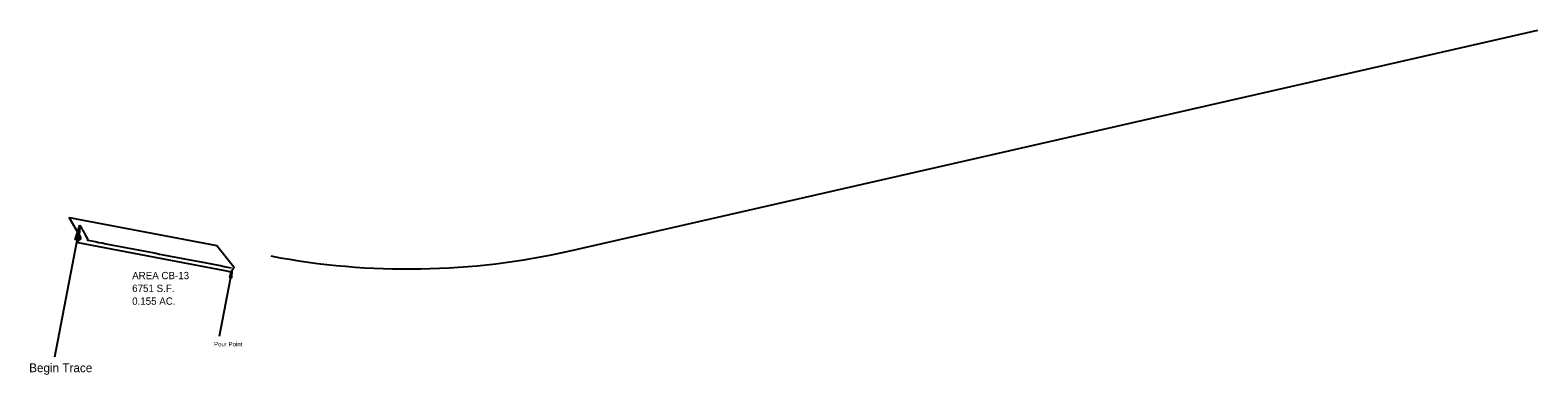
# Model space of a CAD drawing. Extents: x 3422 to 5489, y 2878 to 3350.
import ezdxf

# ---------------------------------------------------------------- set-up
doc = ezdxf.new("R2010")
doc.units = 0
for name, color, linetype in [('Default', 7, 'Continuous'), ('DESIGN - CENTERLINE - Proposed', 7, 'Continuous'), ('DESIGN - SCRATCH - User 1', 7, 'Continuous'), ('SURVEY - CENTERLINE - Preliminary', 7, 'Continuous'), ('SURVEY - CENTERLINE - Preliminary Text', 7, 'Continuous'), ('SURVEY - DRAINAGE - Area Shapes', 7, 'Continuous')]:
    doc.layers.add(name, color=color, linetype=linetype)

msp = doc.modelspace()

# ---------------------------------------------------------------- linework, layer by layer
at = {"layer": 'DESIGN - CENTERLINE - Proposed'}
msp.add_line((4162.4, 3048), (5488.9, 3350.1), dxfattribs=at)
msp.add_arc((3940.3, 4023), 1000, 259.1667, 282.8334, dxfattribs=at)
at = {"layer": 'DESIGN - SCRATCH - User 1'}
msp.add_line((3698.9, 3020.8), (3681.4, 2930.3), dxfattribs=at)
msp.add_lwpolyline([(3698.9, 3020.8), (3698.3, 3010.7), (3697.3, 3012.2), (3695.8, 3011.2)], close=True, dxfattribs=at)
msp.add_lwpolyline([(3698.9, 3020.8), (3698.3, 3010.7), (3697.3, 3012.2), (3695.8, 3011.2), (3698.9, 3020.8)], dxfattribs=at)
at = {"layer": 'SURVEY - CENTERLINE - Preliminary'}
msp.add_lwpolyline([(3490.5, 3082.9), (3491.1, 3081.7), (3493.1, 3078.2), (3493.7, 3077.2), (3494, 3076.7), (3494.8, 3075.3), (3497.8, 3070), (3501, 3064.5), (3501, 3062.6), (3501, 3062.4), (3501.4, 3062.3), (3506.3, 3061.4), (3511.2, 3060.5), (3516.2, 3059.5), (3521.1, 3058.6), (3526, 3057.6), (3530.9, 3056.7), (3535.8, 3055.8), (3540.7, 3054.8), (3545.6, 3053.9), (3550.5, 3052.9), (3555.4, 3052), (3560.3, 3051.1), (3565.3, 3050.1), (3570.2, 3049.2), (3575.1, 3048.2), (3580, 3047.3), (3584.9, 3046.4), (3589.8, 3045.4), (3594.7, 3044.5), (3599.6, 3043.5), (3604.5, 3042.6), (3609.5, 3041.7), (3614.4, 3040.7), (3619.3, 3039.8), (3624.2, 3038.8), (3629.1, 3037.9), (3634, 3037), (3638.9, 3036), (3643.8, 3035.1), (3648.7, 3034.1), (3653.7, 3033.2), (3658.6, 3032.3), (3661.5, 3031.7), (3663.5, 3031.3), (3668.4, 3030.4), (3673.3, 3029.4), (3678.2, 3028.5), (3683.1, 3027.6), (3688, 3026.6), (3692.9, 3025.7), (3697.9, 3024.7)], dxfattribs=at)
at = {"layer": 'SURVEY - CENTERLINE - Preliminary Text'}
msp.add_line((3490.5, 3082.9), (3455.4, 2902), dxfattribs=at)
msp.add_lwpolyline([(3490.5, 3082.9), (3489.1, 3062.7), (3487.1, 3065.7), (3484.1, 3063.6)], close=True, dxfattribs=at)
msp.add_lwpolyline([(3490.5, 3082.9), (3489.1, 3062.7), (3487.1, 3065.7), (3484.1, 3063.6), (3490.5, 3082.9)], dxfattribs=at)
at = {"layer": 'SURVEY - DRAINAGE - Area Shapes'}
for q in [(3678.3, 3055), (3475.9, 3093.7)]:
    msp.add_line((3475.9, 3093.7), q, dxfattribs=at)
for points in [[(3485.7, 3059.3), (3491.6, 3064.2), (3491.6, 3066.3), (3475.9, 3093.7)], [(3678.3, 3055), (3701.4, 3026.1), (3701, 3023.6), (3697.4, 3018.7), (3691.8, 3019.8), (3485.6, 3059.3)]]:
    msp.add_lwpolyline(points, dxfattribs=at)

# ---------------------------------------------------------------- texts
at = {"layer": 'Default'}
for s, p in [('AREA CB-13', (3562.1, 3009)), ('6751 S.F.', (3562.1, 2991.5)), ('0.155 AC.', (3562.1, 2974))]:
    msp.add_text(s, height=10, dxfattribs=at).set_placement(p)
at = {"layer": 'DESIGN - SCRATCH - User 1'}
msp.add_text('Pour Point', height=6, dxfattribs=at).set_placement((3674.4, 2917.1))
at = {"layer": 'SURVEY - CENTERLINE - Preliminary Text'}
msp.add_text('Begin Trace ', height=12, dxfattribs=at).set_placement((3420.9, 2881.6))

doc.saveas('drawing.dxf')
